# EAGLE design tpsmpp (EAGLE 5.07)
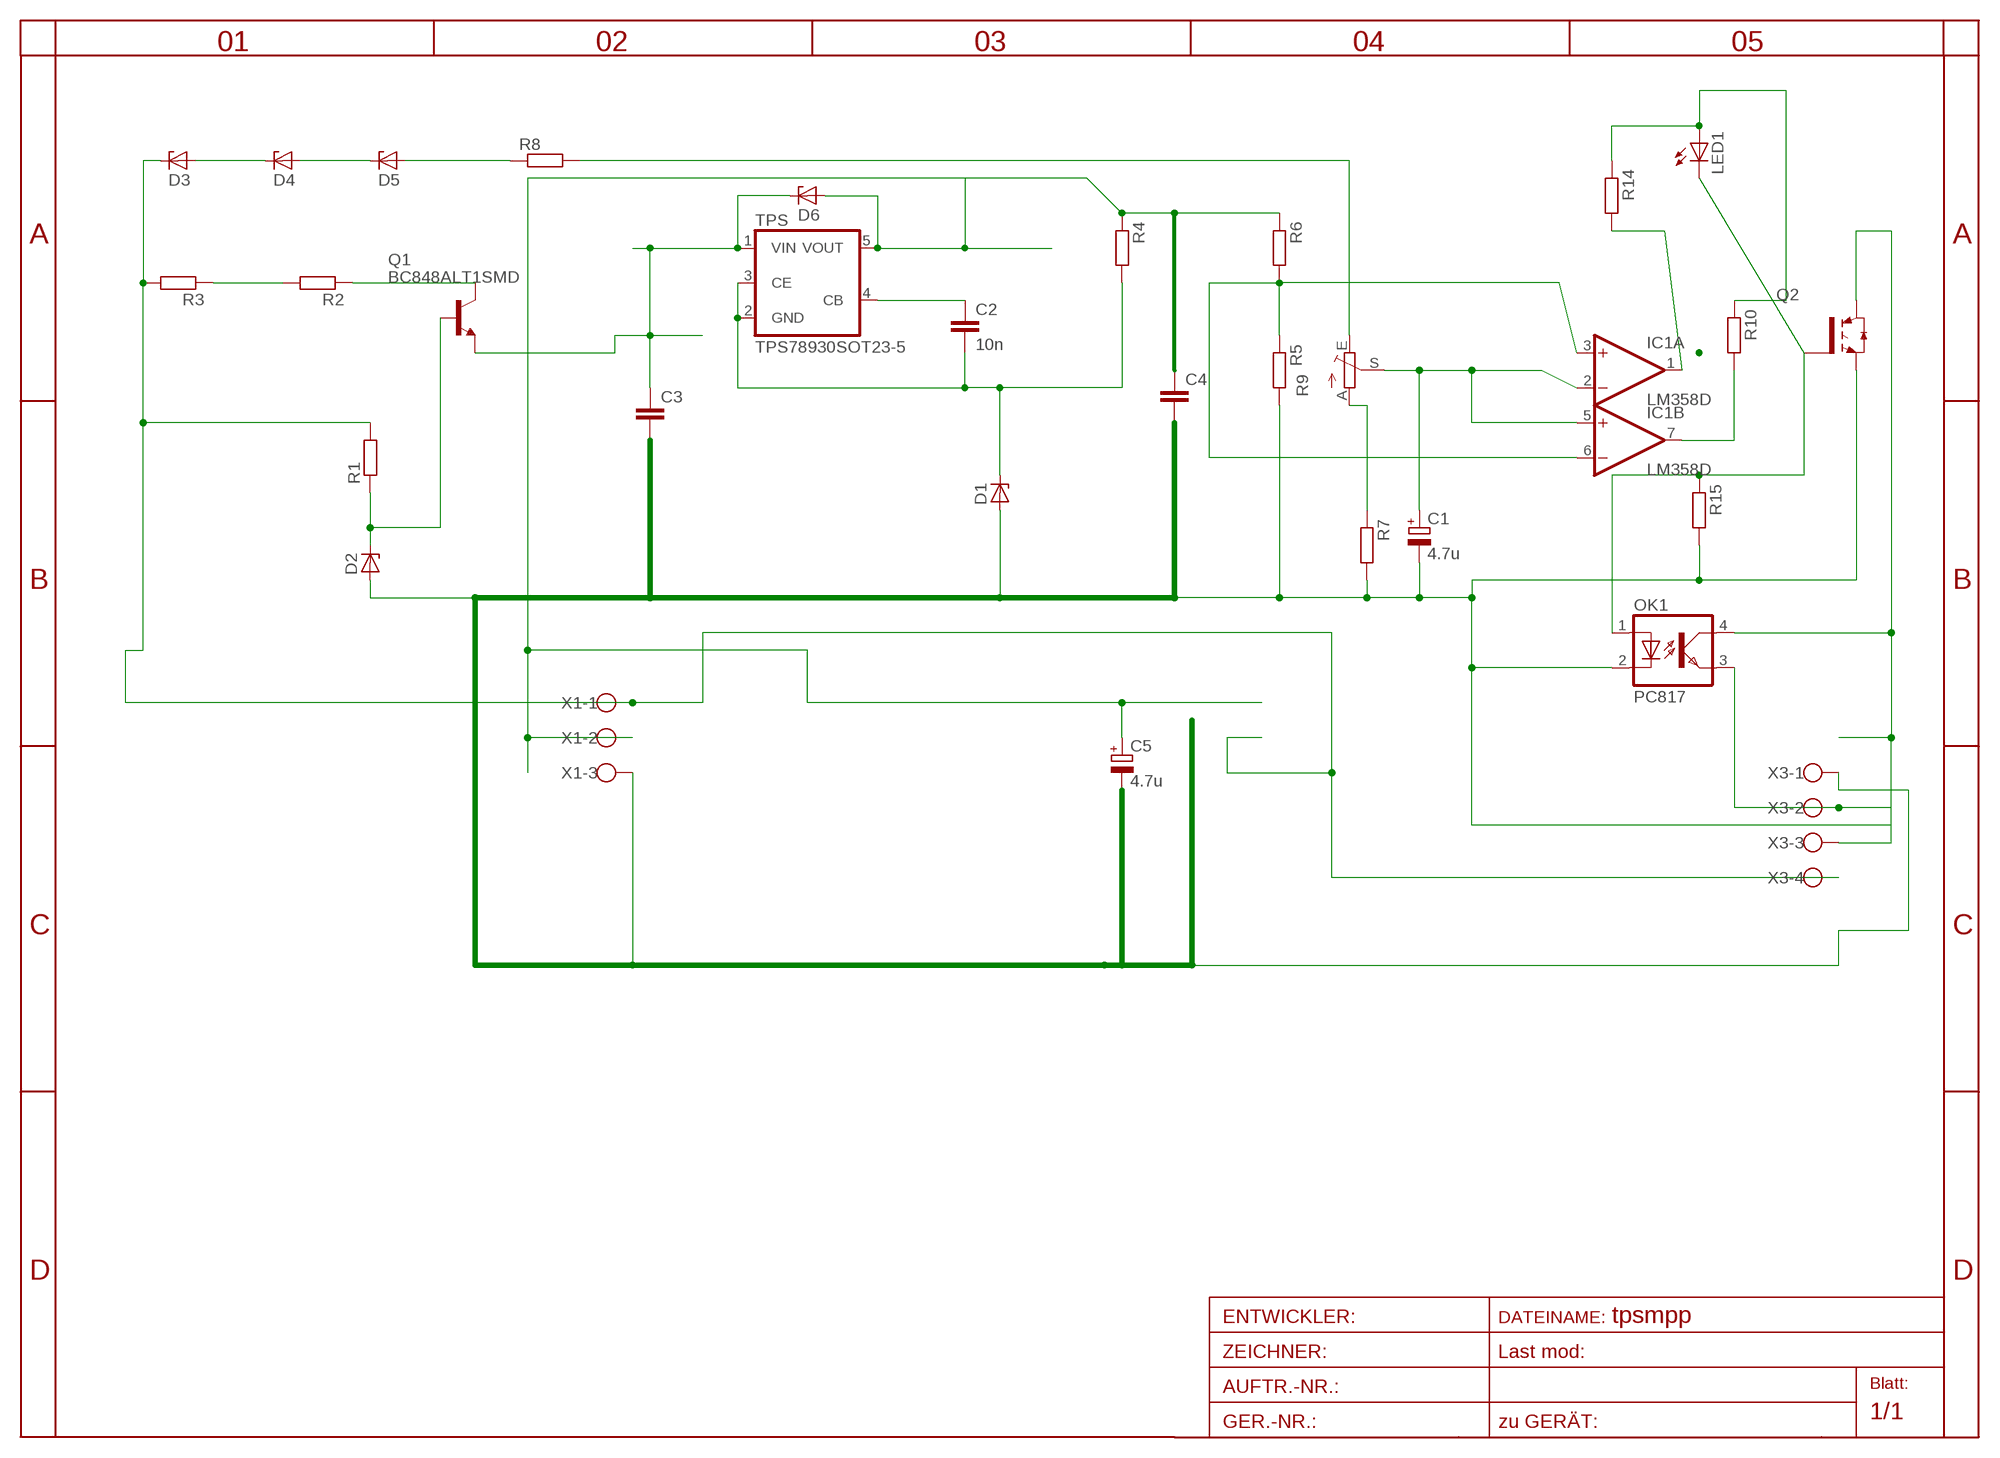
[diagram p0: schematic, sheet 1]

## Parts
C1  4.7u  CPOL-EUSANYO_SMD_C6  [SANYO-OSCON_SMD_C6]
C2  10n  C-EUC0805  [C0805]
C3  C-EUC1206  [C1206]
C4  C-EUC1206  [C1206]
C5  4.7u  CPOL-EUSANYO_SMD_C6  [SANYO-OSCON_SMD_C6]
D1  ZENER-DIODESOD80C  [SOD80C]
D2  ZENER-DIODESOD80C  [SOD80C]
D3  ZENER-DIODESOD80C  [SOD80C]
D4  ZENER-DIODESOD80C  [SOD80C]
D5  ZENER-DIODESOD80C  [SOD80C]
D6  ZENER-DIODESOD80C  [SOD80C]
IC1  LM358D  [SO08]
LED1  LEDCHIPLED_1206  [CHIPLED_1206]
OK1  PC817  [DIL04]
Q1  BC848ALT1SMD  [SOT23]
Q2  IRG4BC15UD-S  [D2PACK]
R1  R-EU_R1206  [R1206]
R2  R-EU_R1206  [R1206]
R3  R-EU_R1206  [R1206]
R4  R-EU_R1206  [R1206]
R5  R-EU_R0805  [R0805]
R6  R-EU_R0805  [R0805]
R7  R-EU_R1206  [R1206]
R8  R-EU_R0805  [R0805]
R9  TRIM_EU-S64W  [S64W]
R10  R-EU_R1206  [R1206]
R14  R-EU_R0805  [R0805]
R15  R-EU_R0805  [R0805]
TPS  TPS78930SOT23-5  [SOT25]
X1  W237-103  [W237-103]
X3  W237-4  [W237-4]

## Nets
A: R7.1 R9.A
E: R8.2 R9.E
GD: C2.2 D1.C R4.2 TPS.2(GND) TPS.3(CE)
IN: D3.C R1.2 R3.2 X1.1 X3.4
IN1: C3.1 D6.C Q1.2(E) TPS.1(VIN)
N$1: C2.1 TPS.4(CB)
N$3: R2.2 R3.1
N$4: Q1.3(C) R2.1
N$5: D2.C Q1.1(B) R1.1
N$6: IC1.3(A:+IN) IC1.6(B:-IN) R5.1 R6.2
N$7: LED1.A R10.1 R14.1
N$8: IC1.7(B:OUT) R10.2
N$13: D5.A R8.1
N$14: D4.A D5.C
N$15: D3.A D4.C
N$17: IC1.1(A:OUT) R14.2
N$19: LED1.C OK1.1(A) Q2.1(G) R15.1
N$23: OK1.3(EMIT) X3.2
OUT-: OK1.4(COL) Q2.2(C) X3.3
S: C1.+ IC1.2(A:-IN) IC1.5(B:+IN) R9.S
V+: C4.1 C5.+ D6.A R4.1 R6.1 TPS.5(VOUT) X1.2
V-: C1.- C3.2 C4.2 C5.- D1.A D2.A OK1.2(C) Q2.3(E) R5.2 R7.2 R15.2 X1.3 X3.1

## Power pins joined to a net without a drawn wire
V+: IC1.8(P:V+)
V-: IC1.4(P:V-)

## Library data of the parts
C1 C5 = rcl:CPOL-EU: POLARIZED CAPACITOR, European symbol
C2-C4 = rcl:C-EU: CAPACITOR, European symbol
D1-D6 = diode:ZENER-DIODE: Z-Diode
IC1 = linear:LM358: OP AMP also LM158; LM258; LM2904 Source: http://cache.national.com/ds/LM/LM158.pdf
LED1 = led:LED: LED
OK1 = optocoupler:PC817: SHARP OPTO COUPLER
Q1 = transistor-npn:BC848*: NPN Transistor
Q2 = transistor-power:IRG4BC15UD-: INSULATED GATE BIPOLAR TRANSISTOR WITH ULTRAFAST SOFT RECOVERY DIODE
R1-R8 R10 R14 R15 = rcl:R-EU_: RESISTOR, European symbol
R9 = pot:TRIM_EU-: POTENTIOMETER
TPS = v-reg:TPS78930
X1 = con-wago-500:W237-103: WAGO SCREW CLAMP
X3 = con-wago-500:W237-4: WAGO SCREW CLAMP

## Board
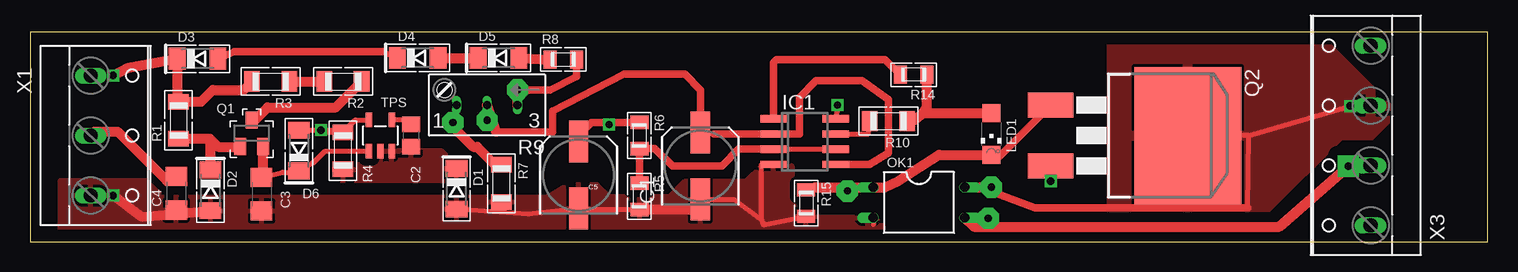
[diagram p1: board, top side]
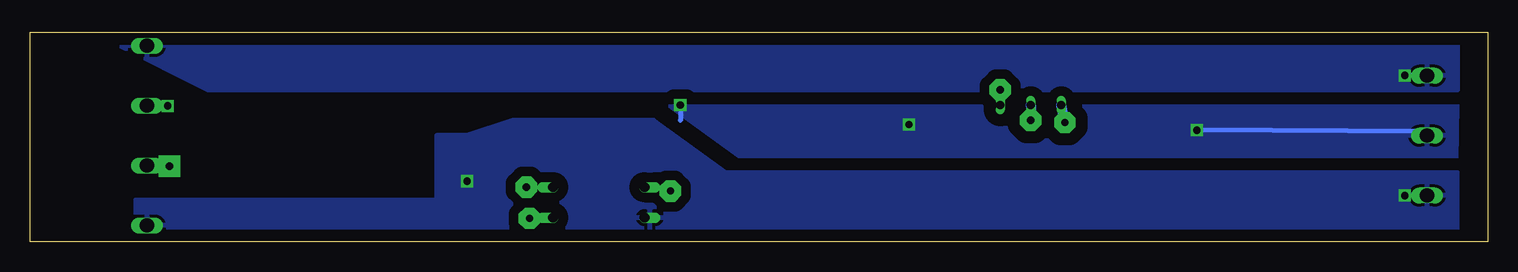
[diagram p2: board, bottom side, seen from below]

Size 121.52 x 17.5 mm. Coordinates in mm from the lower left corner, seen from the top.
Outline: 0,0 121.52,0 121.52,17.5 0,17.5 0,0
Copper layers (1*16): Top 0.035mm / dielectric 1.5mm / Bottom 0.035mm
Design rules "default": minimum track width 10mil, minimum drill 20mil, track to track 8mil, track to pad 8mil, pad to pad 8mil, via to via 8mil, smd to smd 8mil, copper to edge 40mil, drill to drill 8mil, minimum pad ring 1mil, minimum via ring 8mil, stop-mask expansion 4mil, vias tented up to drill 0mil, thermal gap 10mil

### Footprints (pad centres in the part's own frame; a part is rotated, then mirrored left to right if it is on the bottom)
SANYO-OSCON_SMD_C6 = smd 3.5 x 1.6: + 2.8,0; - -2.8,0
C0805 = smd 1.3 x 1.5: 1 -0.95,0; 2 0.95,0
C1206 = smd 1.6 x 1.8: 1 -1.4,0; 2 1.4,0
SOD80C = smd 1.4 x 1.8: A 1.7,0; C -1.7,0
SO08 = smd 0.6 x 2.2: 1 -1.905,-2.6; 2 -0.635,-2.6; 3 0.635,-2.6; 4 1.905,-2.6; 5 1.905,2.6; 6 0.635,2.6; 7 -0.635,2.6; 8 -1.905,2.6
CHIPLED_1206 = smd 1.5 x 1.5: A 0,-1.75; C 0,1.75
DIL04 = drill 0.813 offset: 1 -1.27,-3.81; 2 1.27,-3.81; 3 1.27,3.81; 4 -1.27,3.81
SOT23 = smd 1 x 1.4: 1 -0.95,-1.1; 2 0.95,-1.1; 3 0,1.1
D2PACK = smd 2.083 x 3.81: 1 -2.54,-8.89; 3 2.54,-8.89 | smd 11.43 x 8.89: 2 0,2.54
R1206 = smd 1.3 x 1.7: 1 -1.55,0; 2 1.55,0
R0805 = smd 1.1 x 1.5: 1 -1.1,0; 2 1.1,0
S64W = drill 0.7 long: A 2.54,1.27; E -2.54,1.27; S 0,1.27
SOT25 = smd 0.55 x 1.2: 1 -0.95,-1.3; 2 0,-1.3; 3 0.95,-1.3; 4 0.95,1.3; 5 -0.95,1.3
W237-103 = drill 1.194 long: 1 -5,-1.29; 2 0,-1.29; 3 5,-1.29
W237-4 = drill 1.194 long: 1 -7.5,-1.27; 2 -2.5,-1.27; 3 2.5,-1.27; 4 7.5,-1.27

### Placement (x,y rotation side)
C1  55.88,6.35 90 top
C2  31.75,8.89 270 top
C3  19.3,4 270 top
C4  12.19,4.06 270 top
C5  45.72,5.59 90 top
D1  35.56,4.45 270 top
D2  15.05,4.32 270 top
D3  13.97,15.3 0 top
D4  32.32,15.37 0 top
D5  39.05,15.37 0 top
D6  22.42,7.62 90 top
IC1  64.58,8.38 270 top
LED1  80.14,9.02 180 top
OK1  74.1,3.3 270 top
Q1  18.48,9.08 0 top
Q2  93.98,8.89 270 top
R1  12.38,10.16 90 top
R2  26.1,13.4 180 top
R3  20.07,13.4 180 top
R4  26.1,7.62 270 top
R5  50.8,3.81 270 top
R6  50.8,8.89 270 top
R7  39.31,4.89 270 top
R8  44.45,15.24 0 top
R9  38.1,12.7 180 top
R10  71.56,10.1 180 top
R14  73.66,13.97 180 top
R15  64.71,3.24 270 top
TPS  29.21,8.89 0 top
X1  6.35,8.89 270 top
X3  110.49,8.89 90 top

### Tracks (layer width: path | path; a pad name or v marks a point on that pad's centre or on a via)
A  (via drill 0.6 pad 1.78)
  Top 0.406: 39.28,6.44 R7.1
  Top 0.813: v35.24,9.97 35.62,9.27 36.96,7.94 37.27,7.94 38.77,6.44 39.28,6.44
  Bottom 0.813: v35.24,9.97 R9.A
E  (via drill 0.6 pad 1.78)
  Top 0.61: R8.2 45.55,13.8 43.37,12.7 v40.64,12.7
  Top 0.813: R9.E v40.64,12.7
GD
  pour Top (isolate 0.61, rank 3): 25.4,6.35 26.67,6.35 27.94,7.62 34.29,7.62 35.56,6.35 35.56,5.08 25.4,5.08
IN  (via drill 0.6)
  Top 0.406: 12.27,11.82 R1.2
  Top 0.813: 12.27,11.82 D3.C 8.19,14.54 v6.92,13.91 | R1.2 14.25,11.71 15.24,12.7 17.82,12.7 R3.2
  Bottom 0.406: v6.92,13.91 5.14,13.97 X1.1
  pour Bottom (isolate 0.813): 114.3,16.51 2.54,16.51 2.54,12.7 106.68,12.7
IN1
  Top 0.406: C3.1 21.04,5.83 22.77,5.83 D6.C 23.54,6.6 23.62,6.6 24.61,7.59 TPS.1
  Top 0.813: Q1.2 19.43,5.53 C3.1
N$1
  Top 0.406: TPS.4 31.4,10.19 C2.1
N$3
  Top 0.813: R3.1 R2.2
N$4
  Top 0.813: Q1.3 18.75,10.18 19.81,11.24 25.49,11.24 R2.1
N$5
  Top 0.813: R1.1 15.01,8.61 15.05,8.57 | 15.05,8.57 15.68,7.94 17.49,7.94 Q1.1 | D2.C 15.05,8.57
N$6
  Top 0.406: IC1.3 IC1.6
  Top 0.61: IC1.3 59.05,7.75 57.7,6.33 53.55,6.33 52.07,7.81 R6.2 R5.1
N$7
  Top 0.406: R10.1 73.66,10.16
  Top 0.813: 74.46,10.77 74.76,11.26 R14.1 | 73.66,10.16 74.46,10.77 | 74.46,10.77 LED1.A
N$8
  Top 0.406: IC1.7 69.89,9.02 R10.2
N$9  (via drill 0.6 pad 1.78)
  other vias: 68.14,4.25
N$10  (via drill 0.6 pad 1.78)
  other vias: 80.14,4.57
N$11  (via drill 0.6 pad 1.78)
  other vias: 79.88,1.97
N$13
  Top 0.813: D5.A R8.1
N$14
  Top 0.813: D4.A D5.C
N$15
  Top 0.406: 29.48,15.88 D4.C
  Top 0.61: D3.A 17.02,15.88 29.48,15.88
N$17
  Top 0.61: IC1.1 61.98,14.99 62.23,15.24 71.29,15.24 R14.2
N$19
  Top 0.406: R15.1 65.45,4.57 | LED1.C 80.8,7.14
  Top 0.61: 80.8,7.14 Q2.1
  Top 0.813: LED1.C 75.78,7.27 72.39,5.08 71.25,4.57 OK1.1 65.45,4.57
N$23  (via drill 0.6 pad 1.78)
  Top 0.813: v109.9,6.33 104.14,1.27 78.68,1.27 OK1.3
  Bottom 0.406: v109.9,6.33 X3.2
OUT-  (via drill 0.6)
  Top 0.406: 101.6,8.89 97.79,8.89 96.52,10.16 95.25,8.89 95.25,7.62 Q2.2 | 101.54,2.86 101.6,8.89 | 101.6,8.89 v110.05,11.37
  Top 0.61: 79.25,4.57 83.76,2.86 101.54,2.86
  Top 0.813: OK1.4 79.25,4.57
  Bottom 0.406: X3.3 110.45,11.39 v110.05,11.37
  pour Top (isolate 0.813): 90.17,17.78 106.68,17.78 113.03,11.43 113.03,10.16 111.76,8.89 109.22,8.89 102.87,2.54 90.17,2.54
S  (via drill 0.6 pad 1.78)
  Top 0.406: C1.+ 57.02,9.02
  Top 0.61: 57.02,9.02 IC1.2 64.14,9.02 64.14,12.06 65.53,13.46 69.34,13.46 71.56,11.87 71.56,7.43 69.98,6.48 IC1.5 | C1.+ 55.88,12.7 54.61,14 49.53,14 43.56,10.93 43.56,9.2 38.86,9.2
  Top 0.813: 38.86,9.2 R9.S
  Bottom 0.813: R9.S v38.1,10.16
V+  (via drill 0.6)
  Top 0.406: C5.+ 45.72,8.89 | IC1.8 67.44,11.56 v67.31,11.43 | TPS.5 27.12,10.19 R4.1 25.4,9.17 | 25.4,9.17 24.8,9.17 v24.26,9.34 | D6.A 25.25,9.32 25.4,9.17 | 11.43,5.08 11.81,5.08 C4.1 | X1.2 5.38,9.21 | 48.26,9.99 v48.26,9.8
  Top 0.61: R6.1 48.26,9.99 46.82,9.99 45.72,8.89
  Top 0.813: 11.43,5.08 7.3,9.21 5.38,9.21
  Bottom 0.406: v67.31,11.43 67.31,10.16 | v24.26,9.34 5.38,9.21 X1.2
  pour Bottom (isolate 1.016, rank 4): 2.54,11.43 69.85,12.7 69.85,10.16 68.58,10.16 66.1,6.86 2.6,6.86
V-  (via drill 0.6)
  Top 0.406: OK1.2 70.3,1.44 | R15.2 61.13,1.44 60.96,1.84 | 60.96,1.84 60.96,6.47 IC1.4 | 60.96,1.84 58.68,3.55 C1.- 55.04,2.71 | Q2.3 v85.09,5.08 | R5.2 46.24,2.71 C5.- 41.54,2.33 D1.A | D2.A 15.22,2.11 C4.2
  Top 0.813: R5.2 55.04,2.71 | D2.A 9.32,2.11 v6.92,3.87
  Bottom 0.406: v6.92,3.87 5.14,3.81 X1.3
  pour Bottom (isolate 0.813, rank 2): 2.54,0.32 2.54,5.78 63.5,5.78 69.53,10.16 81.28,10.16 85.09,8.89 87.63,8.89 87.63,3.49 112.71,3.49 112.71,0.64 16.51,0.64
  pour Top (isolate 0.61): 2.54,5.14 10.73,5.14 10.73,3.75 43.18,3.75 43.18,3.81 44.83,4.83 47.24,4.83 48.26,3.81 53.34,3.81 54.61,5.08 59.69,5.08 60.96,6.35 63.5,6.35 63.5,3.3 64.71,2.1 70.29,2.1 71.12,1.27 71.12,0 41.91,0 2.54,-0.25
